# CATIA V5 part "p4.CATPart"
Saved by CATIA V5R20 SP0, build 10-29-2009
Part number: p4
Publications: "Line.1", "Line.2", "Line.3", "Line.4", "Line.5", "Plane.1"
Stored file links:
  D:\Dropbox\IAO_2011\MMS_GR2\IAO_2011_1439_jlicbarski\p4.CATPart
  D:\Dropbox\IAO_2011\MMS_GR2\IAO_2011_1439_jlicbarski\train.CATProduct

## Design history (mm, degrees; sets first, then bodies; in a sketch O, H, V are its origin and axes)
AxisSystem1: origin (0, 0, 0), X (1, 0, 0), Y (0, 1, 0), Z (0, 0, 1)
Set1
  Point1 to Point3: linked copy from another document
Body1 (main body)
  Line1: type PtPt, FirstPoint Point1, SecondPoint Point2
  Line2: type PtPt, FirstPoint Point2, SecondPoint Point3
  Line3: type PtDir, RefPoint Point1, Direction edge [XY plane of AxisSystem1 | ZX plane of AxisSystem1], Start 0, End -10
  Line4: type PtDir, RefPoint Point2, Direction edge [XY plane of AxisSystem1 | ZX plane of AxisSystem1], Start 0, End -10
  Line5: type PtDir, RefPoint Point3, Direction edge [XY plane of AxisSystem1 | ZX plane of AxisSystem1], Start 0, End -10
  Plane1: type Normal, Curve Line3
